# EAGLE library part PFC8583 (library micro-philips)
I2C-Bus CLOCK/CALENDAR
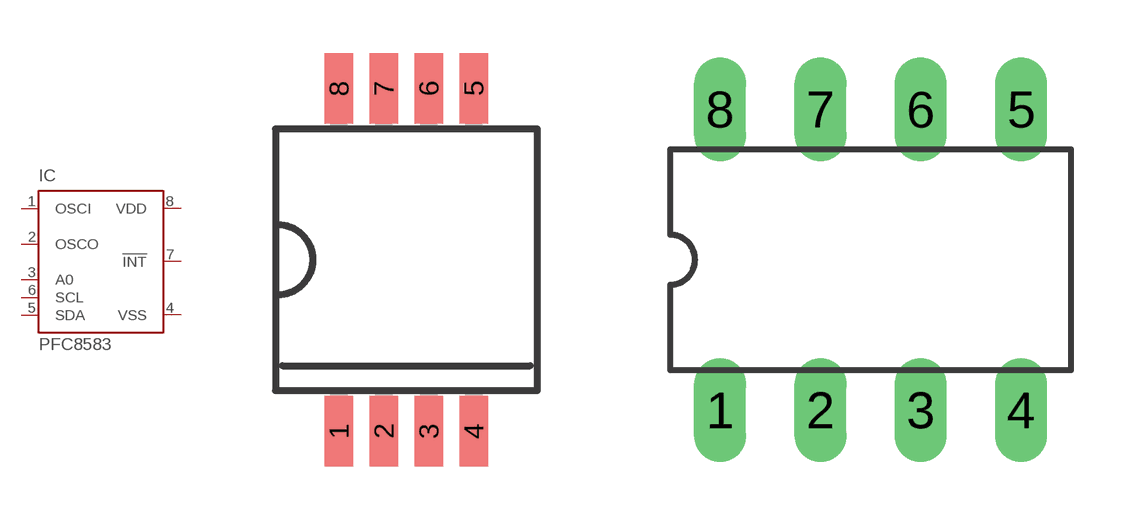
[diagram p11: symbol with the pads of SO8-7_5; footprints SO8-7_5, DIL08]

Designator prefix IC

## PFC8583T (OC_FARNELL: unknown; OC_NEWARK: unknown)  [SO8-7_5]
1  OSCI  in
2  OSCO  out
3  A0  in
4  VSS  pwr
5  SDA
6  SCL  in
7  !INT  out
8  VDD  pwr

## PFC8583P (OC_FARNELL: unknown; OC_NEWARK: unknown)  [DIL08]
Pads as for SO8-7_5

## Footprint SO8-7_5 (pad centres in mm)
Small Outline Package
smd 0.8 x 2: 1 -1.905,-4.845; 2 -0.635,-4.845; 3 0.635,-4.845; 4 1.905,-4.845; 5 1.905,4.845; 6 0.635,4.845; 7 -0.635,4.845; 8 -1.905,4.845

## Footprint DIL08 (pad centres in mm)
Dual In Line
drill 0.813 long: 1 -3.81,-3.81; 2 -1.27,-3.81; 3 1.27,-3.81; 4 3.81,-3.81; 5 3.81,3.81; 6 1.27,3.81; 7 -1.27,3.81; 8 -3.81,3.81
